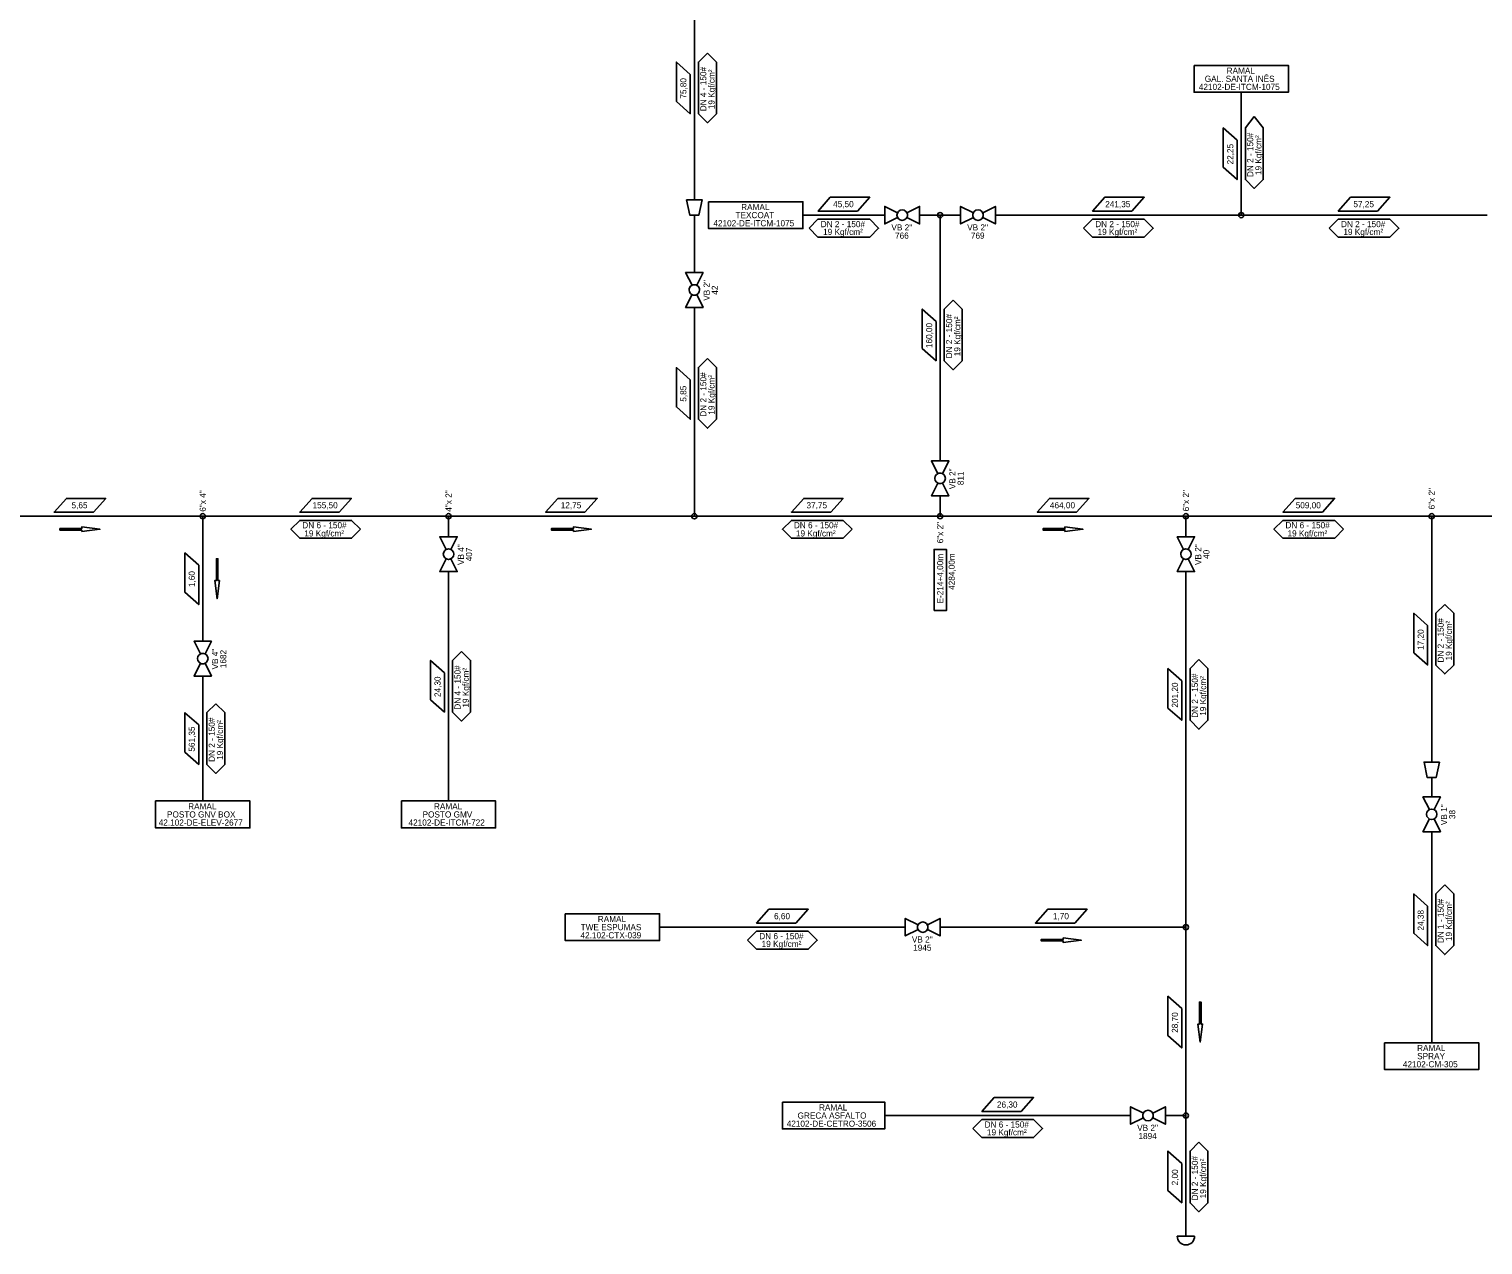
# Model space of a CAD drawing. Extents: x -39999 to 23586, y -25927 to 32541.
# Drawn here: x -39145 to -38435, y -348 to 246 of the extents above; entities that cross this region are included whole.
import ezdxf

# ---------------------------------------------------------------- set-up
doc = ezdxf.new("R2010")
doc.units = 0
for name, color, linetype in [('FLUXOGRAMA', 7, 'Continuous'), ('LEGENDA', 7, 'Continuous'), ('SIMBOLO', 7, 'Continuous'), ('TEXTO', 7, 'Continuous'), ('TUBO_ACO_GN_2', 7, 'Continuous'), ('TUBO_ACO_GN_4', 7, 'Continuous'), ('TUBO_ACO_GN_6', 7, 'Continuous'), ('VALVULA_ACO_2', 7, 'Continuous'), ('VALVULA_ACO_4', 7, 'Continuous')]:
    doc.layers.add(name, color=color, linetype=linetype)

# ---------------------------------------------------------------- blocks, each defined once
blk = doc.blocks.new('VALVULA_DN_4')
at = {"layer": 'VALVULA_ACO_4'}
for points in [[(-1.14, 0.57), (-4.25, 2.13), (-4.25, -2.13), (-1.14, -0.57)], [(-1.14, -0.57), (-4.25, -2.13), (-4.25, 2.13), (-1.14, 0.57)], [(1.14, -0.57), (4.25, -2.13), (4.25, 2.13), (1.14, 0.57)], [(1.14, -0.57), (4.25, -2.13), (4.25, 2.13), (1.14, 0.57)]]:
    blk.add_lwpolyline(points, dxfattribs=at)
blk.add_circle((0, 0), 1.28, dxfattribs=at)
for start, end in [(90, 270), (153.4349, 206.5651), (270, 90), (0, 26.5651), (333.4349, 0)]:
    blk.add_arc((0, 0), 1.28, start, end, dxfattribs=at)
blk = doc.blocks.new('VALVULA_ACO_2')
at = {"layer": 'VALVULA_ACO_2'}
for points in [[(-1.14, 0.57), (-4.25, 2.13), (-4.25, -2.13), (-1.14, -0.57)], [(-1.14, -0.57), (-4.25, -2.13), (-4.25, 2.13), (-1.14, 0.57)], [(1.14, -0.57), (4.25, -2.13), (4.25, 2.13), (1.14, 0.57)], [(1.14, -0.57), (4.25, -2.13), (4.25, 2.13), (1.14, 0.57)]]:
    blk.add_lwpolyline(points, dxfattribs=at)
blk.add_circle((0, 0), 1.28, dxfattribs=at)
for start, end in [(90, 270), (153.4349, 206.5651), (270, 90), (0, 26.5651), (333.4349, 0)]:
    blk.add_arc((0, 0), 1.28, start, end, dxfattribs=at)

msp = doc.modelspace()

# ---------------------------------------------------------------- linework, layer by layer
msp.add_lwpolyline([(-38703.18, -38.17), (-38703.18, -8.25), (-38697.18, -8.25), (-38697.18, -38.17)], close=True)
at = {"layer": 'FLUXOGRAMA'}
for p, q in [((-38460.27, -119.59), (-38460.27, -129.1)), ((-38460.27, -146.11), (-38460.27, -249.1))]:
    msp.add_line(p, q, dxfattribs=at)
for points in [[(-38461.41, -135.32), (-38464.52, -129.1), (-38456.01, -129.1), (-38459.13, -135.32)], [(-38461.41, -139.89), (-38464.52, -146.11), (-38456.01, -146.11), (-38459.13, -139.89)]]:
    msp.add_lwpolyline(points, dxfattribs=at)
msp.add_circle((-38460.27, -137.6), 2.55, dxfattribs=at)
for start, end in [(0, 180), (180, 0)]:
    msp.add_arc((-38460.27, -137.6), 2.55, start, end, dxfattribs=at)
at = {"layer": 'LEGENDA'}
for points in [[(-39119.32, 0.42), (-39119.32, 1.17), (-39130.01, 1.17), (-39130.01, 1.92), (-39119.32, 1.92), (-39119.32, 2.67), (-39110.52, 1.54)], [(-39119.32, 0.42), (-39119.32, 1.17), (-39130.01, 1.17), (-39130.01, 1.92), (-39119.32, 1.92), (-39119.32, 2.67), (-39110.52, 1.54)], [(-38879.32, 0.42), (-38879.32, 1.17), (-38890.01, 1.17), (-38890.01, 1.92), (-38879.32, 1.92), (-38879.32, 2.67), (-38870.52, 1.54)], [(-38879.32, 0.42), (-38879.32, 1.17), (-38890.01, 1.17), (-38890.01, 1.92), (-38879.32, 1.92), (-38879.32, 2.67), (-38870.52, 1.54)], [(-38639.32, 0.42), (-38639.32, 1.17), (-38650.01, 1.17), (-38650.01, 1.92), (-38639.32, 1.92), (-38639.32, 2.67), (-38630.52, 1.54)], [(-38639.32, 0.42), (-38639.32, 1.17), (-38650.01, 1.17), (-38650.01, 1.92), (-38639.32, 1.92), (-38639.32, 2.67), (-38630.52, 1.54)], [(-39053.27, -32.33), (-39052.14, -23.53), (-39052.89, -23.53), (-39052.89, -12.84), (-39053.64, -12.84), (-39053.64, -23.53), (-39054.39, -23.53)], [(-39052.14, -23.53), (-39052.89, -23.53), (-39052.89, -12.84), (-39053.64, -12.84), (-39053.64, -23.53), (-39054.39, -23.53), (-39053.27, -32.33)], [(-38640.17, -200.2), (-38640.17, -199.45), (-38650.86, -199.45), (-38650.86, -198.7), (-38640.17, -198.7), (-38640.17, -197.95), (-38631.37, -199.07)], [(-38640.17, -197.95), (-38640.17, -198.7), (-38650.86, -198.7), (-38650.86, -199.45), (-38640.17, -199.45), (-38640.17, -200.2), (-38631.37, -199.07)], [(-38573.27, -248.8), (-38572.14, -240), (-38572.89, -240), (-38572.89, -229.31), (-38573.64, -229.31), (-38573.64, -240), (-38574.39, -240)], [(-38572.14, -240), (-38572.89, -240), (-38572.89, -229.31), (-38573.64, -229.31), (-38573.64, -240), (-38574.39, -240), (-38573.27, -248.8)]]:
    msp.add_lwpolyline(points, close=True, dxfattribs=at)
at = {"layer": 'SIMBOLO'}
for points in [[(-38822.27, 223.65), (-38822.27, 204.43), (-38829.02, 210.43), (-38829.02, 229.65)], [(-38576.25, 228.05), (-38530.25, 228.05), (-38530.25, 214.93), (-38576.25, 214.93)], [(-38555.25, 191.54), (-38555.25, 172.32), (-38562, 178.32), (-38562, 197.54)], [(-38740.67, 156.93), (-38759.89, 156.93), (-38753.89, 163.68), (-38734.67, 163.68)], [(-38606.65, 156.93), (-38625.86, 156.93), (-38619.86, 163.68), (-38600.65, 163.68)], [(-38486.65, 156.93), (-38505.86, 156.93), (-38499.86, 163.68), (-38480.65, 163.68)], [(-38824.02, 162.43), (-38822.52, 154.93), (-38818.02, 154.93), (-38816.52, 162.43)], [(-38813.28, 161.49), (-38767.28, 161.49), (-38767.28, 148.36), (-38813.28, 148.36)], [(-38702.27, 103.04), (-38702.27, 83.82), (-38709.02, 89.82), (-38709.02, 109.04)], [(-38822.27, 74.52), (-38822.27, 55.31), (-38829.02, 61.31), (-38829.02, 80.52)], [(-39113.66, 9.91), (-39132.88, 9.91), (-39126.88, 16.66), (-39107.66, 16.66)], [(-38993.66, 9.91), (-39012.88, 9.91), (-39006.88, 16.66), (-38987.66, 16.66)], [(-38873.66, 9.91), (-38892.88, 9.91), (-38886.88, 16.66), (-38867.66, 16.66)], [(-38753.66, 9.91), (-38772.88, 9.91), (-38766.88, 16.66), (-38747.66, 16.66)], [(-38633.66, 9.91), (-38652.88, 9.91), (-38646.88, 16.66), (-38627.66, 16.66)], [(-38513.66, 9.91), (-38532.88, 9.91), (-38526.88, 16.66), (-38507.66, 16.66)], [(-39062.27, -15.98), (-39062.27, -35.19), (-39069.02, -29.19), (-39069.02, -9.98)], [(-38462.27, -45.48), (-38462.27, -64.69), (-38469.02, -58.69), (-38469.02, -39.48)], [(-38942.27, -68.49), (-38942.27, -87.71), (-38949.02, -81.71), (-38949.02, -62.49)], [(-38582.27, -72.49), (-38582.27, -91.71), (-38589.02, -85.71), (-38589.02, -66.49)], [(-39062.27, -93.99), (-39062.27, -113.21), (-39069.02, -107.21), (-39069.02, -87.99)], [(-38456.52, -112.09), (-38458.02, -119.59), (-38462.52, -119.59), (-38464.02, -112.09)], [(-39083.27, -131.1), (-39037.27, -131.1), (-39037.27, -144.22), (-39083.27, -144.22)], [(-38963.27, -131.1), (-38917.27, -131.1), (-38917.27, -144.22), (-38963.27, -144.22)], [(-38462.27, -182.49), (-38462.27, -201.71), (-38469.02, -195.71), (-38469.02, -176.49)], [(-38770.67, -190.7), (-38789.89, -190.7), (-38783.89, -183.95), (-38764.67, -183.95)], [(-38634.51, -190.7), (-38653.73, -190.7), (-38647.73, -183.95), (-38628.51, -183.95)], [(-38883.28, -186.14), (-38837.28, -186.14), (-38837.28, -199.26), (-38883.28, -199.26)], [(-38582.27, -232.44), (-38582.27, -251.66), (-38589.02, -245.66), (-38589.02, -226.44)], [(-38483.27, -249.1), (-38437.27, -249.1), (-38437.27, -262.22), (-38483.27, -262.22)], [(-38660.67, -282.67), (-38679.89, -282.67), (-38673.89, -275.92), (-38654.67, -275.92)], [(-38777.28, -278.11), (-38727.28, -278.11), (-38727.28, -291.23), (-38777.28, -291.23)], [(-38582.27, -308.06), (-38582.27, -327.28), (-38589.02, -321.28), (-38589.02, -302.06)]]:
    msp.add_lwpolyline(points, close=True, dxfattribs=at)
for points in [[(-38813.89, 234.04), (-38809.52, 229.66), (-38809.52, 204.41), (-38813.89, 200.04), (-38818.27, 204.41), (-38818.27, 229.66), (-38813.89, 234.04)], [(-38546.88, 203.09), (-38542.51, 197.55), (-38542.51, 172.3), (-38546.88, 167.93), (-38551.25, 172.3), (-38551.25, 197.55), (-38546.88, 203.09)], [(-38764.28, 148.55), (-38759.9, 152.93), (-38734.65, 152.93), (-38730.28, 148.55), (-38734.65, 144.18), (-38759.9, 144.18), (-38764.28, 148.55)], [(-38630.25, 148.55), (-38625.88, 152.93), (-38600.63, 152.93), (-38596.25, 148.55), (-38600.63, 144.18), (-38625.88, 144.18), (-38630.25, 148.55)], [(-38510.25, 148.55), (-38505.88, 152.93), (-38480.63, 152.93), (-38476.25, 148.55), (-38480.63, 144.18), (-38505.88, 144.18), (-38510.25, 148.55)], [(-38693.89, 113.43), (-38689.52, 109.05), (-38689.52, 83.8), (-38693.89, 79.43), (-38698.27, 83.8), (-38698.27, 109.05), (-38693.89, 113.43)], [(-38813.89, 84.91), (-38809.52, 80.54), (-38809.52, 55.29), (-38813.89, 50.91), (-38818.27, 55.29), (-38818.27, 80.54), (-38813.89, 84.91)], [(-38983.27, 1.54), (-38987.64, -2.83), (-39012.89, -2.83), (-39017.27, 1.54), (-39012.89, 5.91), (-38987.64, 5.91), (-38983.27, 1.54)], [(-38743.27, 1.54), (-38747.64, -2.83), (-38772.89, -2.83), (-38777.27, 1.54), (-38772.89, 5.91), (-38747.64, 5.91), (-38743.27, 1.54)], [(-38503.27, 1.54), (-38507.64, -2.83), (-38532.89, -2.83), (-38537.27, 1.54), (-38532.89, 5.91), (-38507.64, 5.91), (-38503.27, 1.54)], [(-38453.89, -35.09), (-38449.52, -39.46), (-38449.52, -64.71), (-38453.89, -69.09), (-38458.27, -64.71), (-38458.27, -39.46), (-38453.89, -35.09)], [(-38933.89, -58.1), (-38929.52, -62.47), (-38929.52, -87.72), (-38933.89, -92.1), (-38938.27, -87.72), (-38938.27, -62.47), (-38933.89, -58.1)], [(-38573.89, -62.1), (-38569.52, -66.47), (-38569.52, -91.72), (-38573.89, -96.1), (-38578.27, -91.72), (-38578.27, -66.47), (-38573.89, -62.1)], [(-39053.89, -83.6), (-39049.52, -87.97), (-39049.52, -113.22), (-39053.89, -117.6), (-39058.27, -113.22), (-39058.27, -87.97), (-39053.89, -83.6)], [(-38453.89, -172.1), (-38449.52, -176.47), (-38449.52, -201.72), (-38453.89, -206.1), (-38458.27, -201.72), (-38458.27, -176.47), (-38453.89, -172.1)], [(-38794.28, -199.07), (-38789.9, -194.7), (-38764.65, -194.7), (-38760.28, -199.07), (-38764.65, -203.45), (-38789.9, -203.45), (-38794.28, -199.07)], [(-38684.28, -291.05), (-38679.9, -286.67), (-38654.65, -286.67), (-38650.28, -291.05), (-38654.65, -295.42), (-38679.9, -295.42), (-38684.28, -291.05)], [(-38573.89, -297.67), (-38569.52, -302.05), (-38569.52, -327.3), (-38573.89, -331.67), (-38578.27, -327.3), (-38578.27, -302.05), (-38573.89, -297.67)]]:
    msp.add_lwpolyline(points, dxfattribs=at)
for centre in [(-38700.27, 154.93), (-38553.25, 154.93), (-39060.27, 7.91), (-38940.27, 7.91), (-38820.27, 7.91), (-38700.27, 7.91), (-38580.27, 7.91), (-38460.27, 7.91), (-38580.27, -192.7), (-38580.27, -284.67)]:
    msp.add_circle(centre, 1.27, dxfattribs=at)
at = {"layer": 'TUBO_ACO_GN_2'}
for p, q in [((-38553.25, 214.93), (-38553.25, 154.93)), ((-38820.27, 126.92), (-38820.27, 154.93)), ((-38727.28, 154.93), (-38767.28, 154.93)), ((-38690.27, 154.93), (-38710.27, 154.93)), ((-38700.27, 34.93), (-38700.27, 154.93)), ((-38433.25, 154.93), (-38673.25, 154.93)), ((-38820.27, 7.91), (-38820.27, 109.9)), ((-38700.27, 7.91), (-38700.27, 17.91)), ((-38580.27, 7.91), (-38580.27, -2.09)), ((-38460.27, -112.09), (-38460.27, 7.91)), ((-38580.27, -19.1), (-38580.27, -343.58)), ((-38717.28, -192.7), (-38837.28, -192.7)), ((-38580.27, -192.7), (-38700.27, -192.7)), ((-38607.28, -284.67), (-38727.28, -284.67)), ((-38580.27, -284.67), (-38590.27, -284.67)), ((-38576.01, -343.58), (-38584.52, -343.58))]:
    msp.add_line(p, q, dxfattribs=at)
msp.add_arc((-38580.27, -343.58), 4.25, 180, 0, dxfattribs=at)
at = {"layer": 'TUBO_ACO_GN_4'}
for p, q in [((-38820.27, 162.43), (-38820.27, 522.43)), ((-39060.27, -53.09), (-39060.27, 7.91)), ((-38940.27, -2.09), (-38940.27, 7.91)), ((-38940.27, -131.1), (-38940.27, -19.1)), ((-39060.27, -131.1), (-39060.27, -70.1))]:
    msp.add_line(p, q, dxfattribs=at)
at = {"layer": 'TUBO_ACO_GN_6'}
msp.add_line((-37980.27, 7.91), (-39420.27, 7.91), dxfattribs=at)

# ---------------------------------------------------------------- block references
at = {"layer": 'VALVULA_ACO_2', "xscale": 2, "yscale": 2}
for p in [(-38718.77, 154.93), (-38681.76, 154.93), (-38708.77, -192.7), (-38598.77, -284.67)]:
    msp.add_blockref('VALVULA_ACO_2', p, dxfattribs=at)
for p, rotation in [((-38820.27, 118.41), 89.99999999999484), ((-38700.27, 26.42), 90), ((-38580.27, -10.59), 89.99999999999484)]:
    msp.add_blockref('VALVULA_ACO_2', p, dxfattribs=dict(at, rotation=rotation))
at = {"layer": 'VALVULA_ACO_4', "xscale": 2, "yscale": 2, "rotation": 90}
for p in [(-38940.27, -10.59), (-39060.27, -61.59)]:
    msp.add_blockref('VALVULA_DN_4', p, dxfattribs=at)

# ---------------------------------------------------------------- texts
for s, p in [('VB 2"', (-38724.06, 147.43)), ('VB 2"', (-38687.05, 147.43)), ('766', (-38722.27, 143.43)), ('769', (-38685.26, 143.43)), ('VB 2"', (-38714.06, -200.2)), ('1945', (-38713.43, -204.2)), ('VB 2"', (-38604.06, -292.17)), ('1894', (-38603.43, -296.17))]:
    msp.add_text(s, height=3).set_placement(p)
for s, p in [('VB 2"', (-38812.77, 113.12)), ('42', (-38808.77, 116.08)), ('VB 2"', (-38692.77, 21.13)), ('811', (-38688.77, 23.08)), ('VB 4"', (-38932.77, -15.88)), ('VB 2"', (-38572.77, -15.88)), ('407', (-38928.77, -14.09)), ('40', (-38568.77, -12.92)), ('VB 4"', (-39052.77, -66.88)), ('1682', (-39048.77, -66.25))]:
    msp.add_text(s, height=3, rotation=90).set_placement(p)
at = {"layer": 'TEXTO'}
for s, p in [('DN 4 - 150#', (-38814.4, 205.64)), ('75,80', (-38824.14, 211.8)), ('19 Kgf/cm²', (-38810.39, 206.64)), ('DN 2 - 150#', (-38547.39, 173.52)), ('19 Kgf/cm²', (-38543.38, 174.53)), ('22,25', (-38557.13, 179.68)), ('DN 2 - 150#', (-38694.4, 85.02)), ('160,00', (-38704.14, 90.02)), ('19 Kgf/cm²', (-38690.39, 86.03)), ('DN 2 - 150#', (-38814.4, 56.51)), ('5,85', (-38824.14, 63.84)), ('19 Kgf/cm²', (-38810.39, 57.51)), ('   6"x 2"  ', (-38458.77, 7.91)), ('  6"x 4"', (-39058.77, 7.91)), ('  4"x 2"', (-38938.77, 7.91)), ('6"x 2"  ', (-38578.77, 10.28)), ('6"x 2"  ', (-38698.77, -5.31)), ('E-214+4,00m', (-38698.77, -34.66)), ('4284,00m', (-38693.12, -28.02)), ('1,60', (-39064.14, -26.66)), ('DN 2 - 150#', (-38454.4, -63.49)), ('17,20', (-38464.14, -57.33)), ('19 Kgf/cm²', (-38450.39, -62.49)), ('24,30', (-38944.14, -80.34)), ('DN 4 - 150#', (-38934.4, -86.5)), ('19 Kgf/cm²', (-38930.39, -85.5)), ('DN 2 - 150#', (-38574.4, -90.5)), ('19 Kgf/cm²', (-38570.39, -89.5)), ('201,20', (-38584.14, -85.5)), ('DN 2 - 150#', (-39054.4, -112)), ('19 Kgf/cm²', (-39050.39, -111)), ('561,35', (-39064.14, -107)), ('VB 1"', (-38452.77, -142.89)), ('38', (-38448.77, -139.93)), ('24,38', (-38464.14, -194.34)), ('DN 1 - 150#', (-38454.4, -200.5)), ('19 Kgf/cm²', (-38450.39, -199.5)), ('28,70', (-38584.14, -244.3)), ('DN 2 - 150#', (-38574.4, -326.07)), ('2,00', (-38584.14, -318.75)), ('19 Kgf/cm²', (-38570.39, -325.07))]:
    msp.add_text(s, height=3, rotation=90, dxfattribs=at).set_placement(p)
for s, p in [('GAL. SANTA INÊS', (-38571.08, 219.99)), ('RAMAL', (-38560.39, 223.95)), ('42102-DE-ITCM-1075', (-38573.95, 216.03)), ('TEXCOAT', (-38800.18, 153.43)), ('RAMAL', (-38797.41, 157.39)), ('45,50', (-38752.52, 158.8)), ('241,35', (-38619.66, 158.8)), ('57,25', (-38498.5, 158.8)), ('42102-DE-ITCM-1075', (-38810.98, 149.47)), ('DN 2 - 150#', (-38758.57, 149.05)), ('DN 2 - 150#', (-38624.55, 149.05)), ('DN 2 - 150#', (-38504.55, 149.05)), ('19 Kgf/cm²', (-38757.41, 145.25)), ('19 Kgf/cm²', (-38623.39, 145.25)), ('19 Kgf/cm²', (-38503.39, 145.25)), ('5,65', (-39124.34, 11.79)), ('155,50', (-39006.67, 11.79)), ('12,75', (-38885.51, 11.79)), ('37,75', (-38765.51, 11.79)), ('464,00', (-38646.67, 11.79)), ('509,00', (-38526.67, 11.79)), ('DN 6 - 150#', (-39011.67, 2.05)), ('19 Kgf/cm²', (-39010.67, -1.96)), ('DN 6 - 150#', (-38771.67, 2.05)), ('19 Kgf/cm²', (-38770.67, -1.96)), ('DN 6 - 150#', (-38531.67, 2.05)), ('19 Kgf/cm²', (-38530.67, -1.96)), ('RAMAL', (-39067.4, -135.2)), ('RAMAL', (-38947.4, -135.2)), ('42.102-DE-ELEV-2677', (-39081.78, -143.12)), ('POSTO GNV BOX', (-39077.74, -139.16)), ('42102-DE-ITCM-722', (-38959.8, -143.12)), ('POSTO GMV', (-38952.96, -139.16)), ('TWE ESPUMAS', (-38875.77, -194.2)), ('RAMAL', (-38867.41, -190.24)), ('6,60', (-38781.36, -188.82)), ('1,70', (-38645.19, -188.82)), ('42.102-CTX-039', (-38875.85, -198.16)), ('DN 6 - 150#', (-38788.57, -198.57)), ('19 Kgf/cm²', (-38787.41, -202.37)), ('SPRAY', (-38467.37, -257.16)), ('RAMAL', (-38467.4, -253.2)), ('42102-CM-305', (-38474.33, -261.12)), ('GRECA ASFALTO', (-38769.87, -286.17)), ('RAMAL', (-38759.41, -282.21)), ('26,30', (-38672.52, -280.8)), ('42102-DE-CETRO-3506', (-38775.19, -290.13)), ('DN 6 - 150#', (-38678.57, -290.55)), ('19 Kgf/cm²', (-38677.41, -294.35))]:
    msp.add_text(s, height=3, dxfattribs=at).set_placement(p)

doc.saveas('drawing.dxf')
